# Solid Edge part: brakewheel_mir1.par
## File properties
Author: KULL
Template: Iso Metric Part.par
Last saved by: KULL
Revision: 2
Application: Solid Edge
Accuracy: 0,990
Username: KULL
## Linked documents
brakewheel.par
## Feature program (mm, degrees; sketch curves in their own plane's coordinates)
part copy "CopiedPart_1"
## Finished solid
Body 1: solid body, 544 faces, 1066 edges, 432 vertices.
  Faces by surface: torus 226, cylinder 204, blend 72, plane 42
  Edges by curve: circle 742, intersection 216, line 108
Bounding box of the edges (mm; curved faces can reach further): 52.000 x 5.000 x 52.000, from (-26, -123, -3) to (26, -118, 49).
Cylindrical faces by radius (mm): R0.2 x36, R0.7 x36, R0.8 x36, R0.9 x36, R4 x1, R10 x2, R14.7173 x18, R15 x2, R17 x18, R26 x1, R28.4 x18
Toroidal faces (ring radius, tube radius in mm): R0.8 r0.1 x36, R0.9 r0.1 x36, R1 r0.1 x36, R9.8 r0.2 x2, R10.2 r0.2 x2, R14.8 r0.2 x2, R15.1173 r0.4 x36, R15.2 r0.2 x2, R25.8 r0.2 x38, R28 r0.4 x36
Planar faces by outward normal: +y 21, -y 21
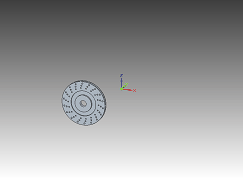
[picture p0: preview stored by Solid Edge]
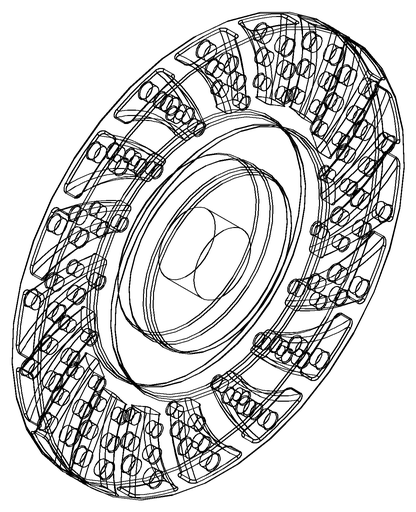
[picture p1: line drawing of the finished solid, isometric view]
